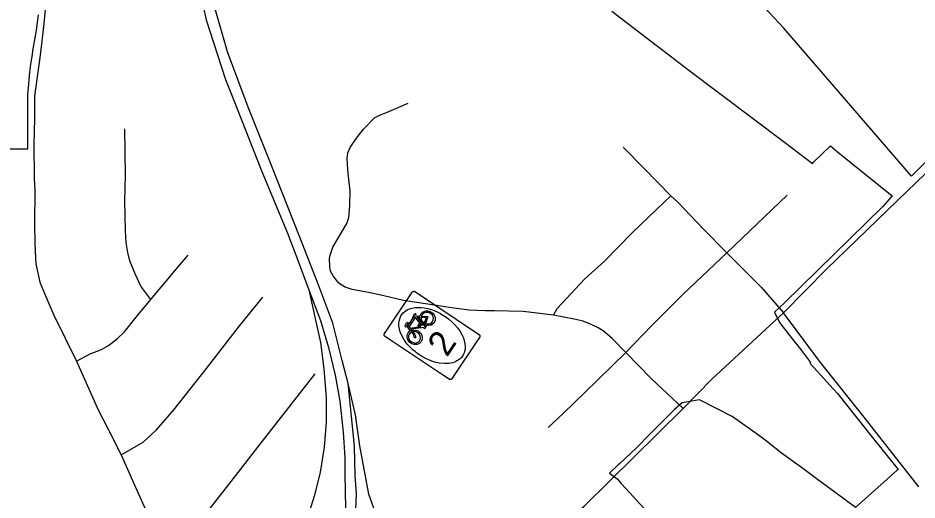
# Model space of a CAD drawing. Extents: x 1716282 to 1717158, y 799307 to 801078.
# Drawn here: x 1716557.2 to 1716655.2, y 800912 to 800964.6 of the extents above; entities that cross this region are included whole.
import ezdxf

# ---------------------------------------------------------------- set-up
doc = ezdxf.new("R2010")
doc.units = 0
for name, color, linetype in [('Exist Boundary Political City Limit New', 7, 'Continuous'), ('Exist Road Primary Interstate Divided Center Attributed', 7, 'Continuous'), ('Exist Road Primary Interstate Ramp 1 Lane Attributed', 7, 'Continuous'), ('Exist Road Primary NC Shield Bike CELL', 7, 'Continuous'), ('Exist Road Primary NC Shield Bike NC Label', 7, 'Continuous'), ('Exist Road Secondary Type 51 Attributed', 7, 'Continuous')]:
    doc.layers.add(name, color=color, linetype=linetype)

msp = doc.modelspace()

# ---------------------------------------------------------------- linework, layer by layer
at = {"layer": 'Exist Boundary Political City Limit New'}
for points in [[(1716657.275, 800950.031), (1716654.634, 800947.36), (1716640.71, 800963.516), (1716631.189, 800973.717)], [(1716558.592, 800959.578), (1716558.712, 800960.427), (1716558.849, 800961.274), (1716559.141, 800962.879), (1716559.208, 800963.295), (1716559.321, 800964.132), (1716559.403, 800964.971)], [(1716621.937, 800965.377), (1716626.775, 800961.667), (1716626.897, 800961.573), (1716630.211, 800959.031), (1716637.247, 800953.729), (1716640.783, 800951.072), (1716643.836, 800948.77), (1716643.992, 800948.924), (1716645.775, 800950.685), (1716646.547, 800950.044), (1716652.529, 800945.232), (1716651.495, 800944.059), (1716640.758, 800933.54), (1716639.686, 800932.523)], [(1716555.958, 800950.356), (1716558.256, 800950.336), (1716558.266, 800956.3), (1716558.316, 800957.018), (1716558.393, 800957.873), (1716558.485, 800958.727), (1716558.592, 800959.578)], [(1716639.686, 800932.523), (1716640.226, 800931.426), (1716641.77, 800929.441), (1716642.361, 800928.682), (1716642.618, 800928.353), (1716643.628, 800927.052), (1716643.522, 800926.985), (1716644.743, 800925.651), (1716646.078, 800924.188), (1716646.556, 800923.663), (1716648.677, 800921), (1716650.06, 800919.262), (1716653.157, 800915.374), (1716653.08, 800915.305), (1716648.52, 800911.218), (1716646.399, 800912.785), (1716644.357, 800914.292), (1716642.619, 800915.574), (1716640.465, 800917.166), (1716638.972, 800918.371), (1716637.925, 800919.118), (1716635.055, 800921.163), (1716631.517, 800922.962), (1716629.6, 800922.655), (1716628.789, 800921.922), (1716627.37, 800920.5), (1716626.095, 800919.214), (1716624.653, 800917.761), (1716622.784, 800916.005), (1716622.644, 800915.873), (1716621.705, 800914.981), (1716622.525, 800914.353), (1716622.556, 800914.319), (1716622.939, 800913.89), (1716623.902, 800912.836), (1716626.132, 800910.395)]]:
    msp.add_lwpolyline(points, dxfattribs=at)
at = {"layer": 'Exist Road Primary Interstate Divided Center Attributed'}
for points in [[(1716579.425, 801012.678), (1716579.169, 801010.216), (1716577.851, 801000), (1716576.584, 800989.759), (1716575.993, 800983.763), (1716575.812, 800980.41), (1716575.906, 800976.338), (1716576.429, 800971.055), (1716577.378, 800965.895), (1716577.712, 800964.422), (1716579.817, 800957.916), (1716580.682, 800955.743), (1716583.712, 800948.077), (1716586.559, 800941.169), (1716587.612, 800938.406), (1716588.881, 800934.972)], [(1716593.968, 800914.692), (1716593.874, 800917.917), (1716593.177, 800924.752), (1716592.547, 800927.261), (1716591.523, 800931.352), (1716590.005, 800935.392), (1716587.849, 800940.895), (1716584.749, 800948.703), (1716582.265, 800954.892), (1716580.032, 800960.917), (1716578.598, 800965.887), (1716578.28, 800967.313), (1716577.69, 800970.883), (1716577.085, 800976.472), (1716576.956, 800980.014), (1716577.097, 800983.057), (1716577.536, 800988.4), (1716579.004, 801001.115), (1716580.238, 801009.156), (1716580.647, 801012.649)], [(1716588.881, 800934.972), (1716590.168, 800931.644), (1716591.055, 800928.695), (1716591.758, 800925.665), (1716592.265, 800922.815), (1716592.639, 800919.43), (1716592.822, 800916.683), (1716592.838, 800914.908), (1716592.899, 800911.15), (1716592.697, 800907.981), (1716592.405, 800905.231), (1716591.573, 800898.947)], [(1716592.721, 800899.289), (1716593.398, 800903.841), (1716593.898, 800908.305), (1716594.083, 800912.742), (1716593.968, 800914.692)]]:
    msp.add_lwpolyline(points, dxfattribs=at)
at = {"layer": 'Exist Road Primary Interstate Ramp 1 Lane Attributed'}
for points in [[(1716588.881, 800934.972), (1716590.181, 800929.215), (1716590.552, 800926.361), (1716590.805, 800923.199), (1716590.8, 800920.537), (1716590.57, 800917.804), (1716590.135, 800915.074), (1716589.53, 800912.576), (1716588.706, 800910.018), (1716587.272, 800906.327), (1716586.565, 800904.298), (1716585.995, 800902.34), (1716585.623, 800900.456), (1716585.498, 800899.473), (1716585.603, 800897.063)], [(1716600.077, 800901.518), (1716597.452, 800906.978), (1716596.236, 800910.427), (1716595.455, 800912.668), (1716594.468, 800917.964), (1716593.976, 800921.344), (1716593.177, 800924.752)]]:
    msp.add_lwpolyline(points, dxfattribs=at)
at = {"layer": 'Exist Road Primary NC Shield Bike CELL'}
for points in [[(1716597.135, 800930.188), (1716597.144, 800930.204), (1716597.544, 800930.8), (1716599.762, 800934.115), (1716600.162, 800934.712), (1716600.178, 800934.732), (1716600.188, 800934.742), (1716600.2, 800934.754), (1716600.212, 800934.765), (1716600.225, 800934.774), (1716600.254, 800934.79), (1716600.268, 800934.796), (1716600.283, 800934.802), (1716600.303, 800934.808), (1716600.333, 800934.813), (1716600.355, 800934.814), (1716600.366, 800934.814), (1716600.375, 800934.813), (1716600.388, 800934.812), (1716600.398, 800934.81), (1716600.409, 800934.808), (1716600.425, 800934.804), (1716600.445, 800934.797), (1716600.463, 800934.789), (1716600.47, 800934.785), (1716600.477, 800934.781), (1716601.082, 800934.376), (1716606.864, 800930.507), (1716607.462, 800930.106), (1716607.483, 800930.09), (1716607.493, 800930.081), (1716607.504, 800930.069), (1716607.515, 800930.056), (1716607.525, 800930.043), (1716607.541, 800930.015), (1716607.547, 800930), (1716607.553, 800929.985), (1716607.559, 800929.965), (1716607.561, 800929.952), (1716607.563, 800929.935), (1716607.564, 800929.926), (1716607.565, 800929.913), (1716607.564, 800929.902), (1716607.564, 800929.893), (1716607.562, 800929.881), (1716607.559, 800929.86), (1716607.554, 800929.843), (1716607.548, 800929.823), (1716607.544, 800929.815), (1716607.539, 800929.806), (1716607.536, 800929.798), (1716607.532, 800929.791), (1716607.526, 800929.781), (1716607.126, 800929.185), (1716604.908, 800925.871), (1716604.509, 800925.275), (1716604.501, 800925.264), (1716604.493, 800925.255), (1716604.484, 800925.244), (1716604.472, 800925.233), (1716604.459, 800925.222), (1716604.446, 800925.212), (1716604.431, 800925.204), (1716604.418, 800925.196), (1716604.404, 800925.19), (1716604.388, 800925.184), (1716604.379, 800925.181), (1716604.368, 800925.178), (1716604.361, 800925.177), (1716604.347, 800925.175), (1716604.336, 800925.173), (1716604.323, 800925.173), (1716604.311, 800925.172), (1716604.3, 800925.173), (1716604.287, 800925.174), (1716604.274, 800925.176), (1716604.262, 800925.178), (1716604.256, 800925.18), (1716604.249, 800925.182), (1716604.244, 800925.183), (1716604.239, 800925.185), (1716604.234, 800925.187), (1716604.229, 800925.188), (1716604.224, 800925.191), (1716604.219, 800925.193), (1716604.214, 800925.195), (1716604.209, 800925.197), (1716604.205, 800925.199), (1716604.2, 800925.202), (1716604.188, 800925.209), (1716603.588, 800925.61), (1716597.805, 800929.48), (1716597.209, 800929.88), (1716597.189, 800929.896), (1716597.178, 800929.906), (1716597.167, 800929.918), (1716597.156, 800929.93), (1716597.146, 800929.943), (1716597.13, 800929.972), (1716597.124, 800929.986), (1716597.118, 800930.001), (1716597.113, 800930.021), (1716597.108, 800930.051), (1716597.106, 800930.073), (1716597.107, 800930.084), (1716597.108, 800930.093), (1716597.109, 800930.106), (1716597.11, 800930.116), (1716597.112, 800930.127), (1716597.117, 800930.143), (1716597.123, 800930.163), (1716597.132, 800930.181)], [(1716605.665, 800927.764), (1716605.605, 800927.683), (1716605.545, 800927.607), (1716605.394, 800927.448), (1716605.183, 800927.294), (1716605.047, 800927.216), (1716604.928, 800927.156), (1716604.79, 800927.099), (1716604.586, 800927.026), (1716604.17, 800926.947), (1716603.681, 800926.92), (1716603.119, 800926.987), (1716602.643, 800927.09), (1716602.21, 800927.242), (1716601.584, 800927.514), (1716601.121, 800927.775), (1716600.904, 800927.917), (1716600.75, 800928.025), (1716600.642, 800928.105), (1716600.481, 800928.23), (1716600.24, 800928.428), (1716600.007, 800928.653), (1716599.862, 800928.803), (1716599.783, 800928.891), (1716599.641, 800929.056), (1716599.52, 800929.205), (1716599.244, 800929.596), (1716599.028, 800929.997), (1716598.876, 800930.382), (1716598.78, 800930.696), (1716598.723, 800931.034), (1716598.723, 800931.268), (1716598.729, 800931.383), (1716598.742, 800931.513), (1716598.775, 800931.716), (1716598.852, 800931.934), (1716598.939, 800932.122), (1716599.028, 800932.263), (1716599.18, 800932.446), (1716599.374, 800932.614), (1716599.633, 800932.782), (1716599.895, 800932.901), (1716600.162, 800932.978), (1716600.491, 800933.037), (1716600.802, 800933.057), (1716601.156, 800933.044), (1716601.489, 800933.008), (1716601.886, 800932.928), (1716602.28, 800932.81), (1716602.636, 800932.676), (1716602.973, 800932.53), (1716603.254, 800932.381), (1716603.408, 800932.293), (1716603.762, 800932.08), (1716604.118, 800931.818), (1716604.512, 800931.483), (1716604.834, 800931.156), (1716605.141, 800930.798), (1716605.411, 800930.412), (1716605.618, 800930.036), (1716605.752, 800929.722), (1716605.853, 800929.423), (1716605.928, 800929.079), (1716605.953, 800928.792), (1716605.935, 800928.51), (1716605.885, 800928.244), (1716605.833, 800928.092), (1716605.796, 800928.008), (1716605.767, 800927.938), (1716605.725, 800927.865)], [(1716600.213, 800931.923), (1716600.453, 800932.393), (1716600.507, 800932.404), (1716600.558, 800932.333), (1716600.519, 800932.203), (1716600.558, 800932.136), (1716600.99, 800932.112), (1716601.154, 800932.382), (1716601.36, 800932.579), (1716601.651, 800932.679), (1716601.87, 800932.672), (1716601.986, 800932.662), (1716602.148, 800932.601), (1716602.301, 800932.509), (1716602.443, 800932.387), (1716602.538, 800932.276), (1716602.618, 800932.127), (1716602.669, 800932.001), (1716602.686, 800931.814), (1716602.677, 800931.661), (1716602.613, 800931.483), (1716602.553, 800931.384), (1716602.392, 800931.21), (1716602.246, 800931.128), (1716602.154, 800931.102), (1716601.974, 800931.087), (1716601.823, 800931.099), (1716601.547, 800931.162), (1716601.427, 800931.215), (1716601.613, 800931.284), (1716601.861, 800931.27), (1716602.033, 800931.264), (1716602.166, 800931.314), (1716602.325, 800931.421), (1716602.401, 800931.53), (1716602.467, 800931.699), (1716602.481, 800931.887), (1716602.451, 800932.05), (1716602.374, 800932.213), (1716602.209, 800932.36), (1716602.059, 800932.454), (1716601.915, 800932.503), (1716601.762, 800932.514), (1716601.641, 800932.5), (1716601.487, 800932.447), (1716601.385, 800932.366), (1716601.24, 800932.219), (1716601.15, 800932.11), (1716601.895, 800932.068), (1716601.613, 800931.284), (1716601.427, 800931.215), (1716601.73, 800931.908), (1716601.115, 800931.946), (1716601.188, 800931.64), (1716601.488, 800931.364), (1716601.427, 800931.215), (1716601.29, 800931.317), (1716601.115, 800931.516), (1716601.033, 800931.713), (1716600.966, 800931.962), (1716600.716, 800932), (1716601.356, 800931.08), (1716601.428, 800931.218), (1716601.547, 800931.162), (1716601.462, 800930.998), (1716601.578, 800930.969), (1716601.688, 800931.027), (1716601.588, 800930.765), (1716601.48, 800930.756), (1716601.49, 800930.868), (1716600.027, 800930.677), (1716600.094, 800930.588), (1716600.319, 800930.6), (1716600.515, 800930.578), (1716600.702, 800930.524), (1716600.854, 800930.459), (1716600.98, 800930.354), (1716601.133, 800930.198), (1716601.235, 800930.001), (1716601.274, 800929.795), (1716601.267, 800929.596), (1716601.193, 800929.395), (1716601.119, 800929.261), (1716601.016, 800929.144), (1716600.731, 800929.012), (1716600.601, 800928.994), (1716600.344, 800929.017), (1716600.08, 800929.129), (1716599.913, 800929.238), (1716599.793, 800929.379), (1716599.705, 800929.533), (1716599.659, 800929.672), (1716599.625, 800929.854), (1716599.628, 800929.991), (1716599.674, 800930.14), (1716599.747, 800930.275), (1716599.962, 800930.531), (1716600.153, 800930.494), (1716600.439, 800930.181), (1716600.545, 800929.95), (1716600.514, 800929.741), (1716600.408, 800929.72), (1716600.318, 800930.153), (1716600.108, 800930.376), (1716600.043, 800930.334), (1716599.935, 800930.25), (1716599.815, 800930.08), (1716599.779, 800929.961), (1716599.768, 800929.775), (1716599.85, 800929.534), (1716599.987, 800929.361), (1716600.196, 800929.255), (1716600.409, 800929.184), (1716600.567, 800929.169), (1716600.7, 800929.213), (1716600.868, 800929.29), (1716600.968, 800929.393), (1716601.055, 800929.545), (1716601.089, 800929.726), (1716601.048, 800929.929), (1716600.953, 800930.105), (1716600.878, 800930.219), (1716600.752, 800930.32), (1716600.597, 800930.397), (1716600.388, 800930.439), (1716599.962, 800930.531), (1716599.661, 800930.932), (1716599.83, 800930.962), (1716599.949, 800930.804), (1716601.1, 800930.966), (1716600.996, 800931.009), (1716600.836, 800931.018), (1716600.83, 800931.065), (1716600.954, 800931.25), (1716601.063, 800931.127), (1716601.169, 800931.083), (1716600.536, 800932.001), (1716599.83, 800930.962), (1716599.661, 800930.932), (1716599.454, 800930.898), (1716599.401, 800931.083), (1716599.551, 800931.383), (1716599.711, 800931.435), (1716599.749, 800931.324), (1716599.617, 800931.168), (1716599.566, 800931.036), (1716599.607, 800931.046), (1716599.646, 800931.105), (1716599.688, 800931.04), (1716600.413, 800932.104), (1716600.392, 800932.128)]]:
    msp.add_lwpolyline(points, close=True, dxfattribs=at)
at = {"layer": 'Exist Road Secondary Type 51 Attributed'}
msp.add_line((1716634.495, 800939.005), (1716641.084, 800945.304), dxfattribs=at)
for points in [[(1716560.19, 800965.951), (1716560.009, 800964.003), (1716559.596, 800960.582), (1716558.994, 800956.11), (1716558.985, 800953.678), (1716558.916, 800950.854), (1716558.931, 800947.165), (1716559.005, 800945.819), (1716558.964, 800942.185), (1716559.019, 800940.069), (1716559.072, 800938.416), (1716559.143, 800937.807), (1716559.571, 800935.809), (1716560.099, 800934.481), (1716561.083, 800932.203), (1716563.55, 800927.186)], [(1716615.58, 800932.206), (1716612.262, 800932.622), (1716609.098, 800932.67), (1716608.135, 800932.67), (1716606.399, 800932.743), (1716604.727, 800932.982), (1716602.814, 800933.251), (1716599.212, 800933.823), (1716597.066, 800934.332), (1716595.595, 800934.639), (1716593.618, 800935.01), (1716592.87, 800935.261), (1716592.427, 800935.505), (1716592.15, 800935.749), (1716591.915, 800936.037), (1716591.548, 800936.485), (1716591.27, 800937.011), (1716591.18, 800937.463), (1716591.151, 800938.378), (1716591.208, 800938.738), (1716591.506, 800939.642), (1716593.042, 800942.218), (1716593.249, 800942.865), (1716593.386, 800944.153), (1716593.397, 800945.787), (1716593.184, 800947.655), (1716593.131, 800948.642), (1716593.066, 800949.328), (1716593.163, 800949.917), (1716593.416, 800950.509), (1716593.972, 800951.356), (1716594.849, 800952.506), (1716596.057, 800953.743), (1716596.592, 800954.027), (1716597.366, 800954.33), (1716599.726, 800955.332)], [(1716571.681, 800933.911), (1716570.586, 800935.363), (1716569.965, 800936.717), (1716569.362, 800938.151), (1716569.164, 800939.037), (1716568.971, 800940.123), (1716568.897, 800941.442), (1716568.827, 800944.635), (1716568.9, 800947.493), (1716568.849, 800952.53)], [(1716640.652, 800932.446), (1716645.399, 800937.248), (1716654.171, 800945.745), (1716658.026, 800949.474), (1716660.242, 800951.726)], [(1716628.377, 800945.217), (1716625.461, 800948.195), (1716623.165, 800950.544)], [(1716615.58, 800932.206), (1716615.982, 800932.949), (1716619.008, 800936.187), (1716621.13, 800938.093), (1716624.174, 800941.196), (1716626.855, 800943.756), (1716628.377, 800945.217)], [(1716628.377, 800945.217), (1716629.128, 800944.533), (1716631.909, 800941.643), (1716634.495, 800939.005)], [(1716571.681, 800933.911), (1716574.822, 800937.706), (1716575.736, 800938.769)], [(1716623.48, 800928.12), (1716626.258, 800931.032), (1716629.762, 800934.553), (1716634.495, 800939.005)], [(1716634.495, 800939.005), (1716638.213, 800935.258), (1716640.652, 800932.446)], [(1716563.55, 800927.186), (1716565.058, 800927.986), (1716566.291, 800928.479), (1716567.059, 800928.884), (1716568.049, 800929.675), (1716568.788, 800930.395), (1716570.083, 800931.988), (1716571.681, 800933.911)], [(1716568.448, 800916.979), (1716570.836, 800918.372), (1716572.27, 800919.713), (1716574.183, 800921.883), (1716577.744, 800926.402), (1716581.217, 800930.904), (1716583.874, 800934.187)], [(1716629.713, 800922.016), (1716632.854, 800925.223), (1716640.652, 800932.446)], [(1716655.42, 800913.481), (1716654.354, 800914.823), (1716652.088, 800917.725), (1716649.62, 800920.902), (1716644.687, 800927.034), (1716640.652, 800932.446)], [(1716623.48, 800928.12), (1716621.967, 800929.681), (1716621.003, 800930.498), (1716620.445, 800930.836), (1716619.609, 800931.241), (1716618.834, 800931.558), (1716617.847, 800931.79), (1716615.58, 800932.206)], [(1716614.989, 800919.957), (1716616.669, 800921.533), (1716618.965, 800923.738), (1716623.48, 800928.12)], [(1716629.713, 800922.016), (1716626.252, 800925.311), (1716623.48, 800928.12)], [(1716563.55, 800927.186), (1716565.914, 800921.896), (1716567.055, 800919.683), (1716568.448, 800916.979)], [(1716573.169, 800906.706), (1716574.514, 800907.367), (1716575.093, 800907.76), (1716575.655, 800908.281), (1716577.266, 800910.028), (1716580.183, 800913.727), (1716584.099, 800918.788), (1716589.587, 800925.8)], [(1716607.303, 800903.686), (1716611.224, 800905.905), (1716613.796, 800907.534), (1716615.721, 800908.822), (1716617.208, 800909.985), (1716618.918, 800911.385), (1716629.713, 800922.016)], [(1716568.448, 800916.979), (1716569.81, 800913.845), (1716571.428, 800910.275), (1716573.169, 800906.706)]]:
    msp.add_lwpolyline(points, dxfattribs=at)

# ---------------------------------------------------------------- texts
at = {"layer": 'Exist Road Primary NC Shield Bike NC Label'}
msp.add_text('2', height=2.773, rotation=56.20506, dxfattribs=at).set_placement((1716603.963, 800927.55))

doc.saveas('drawing.dxf')
